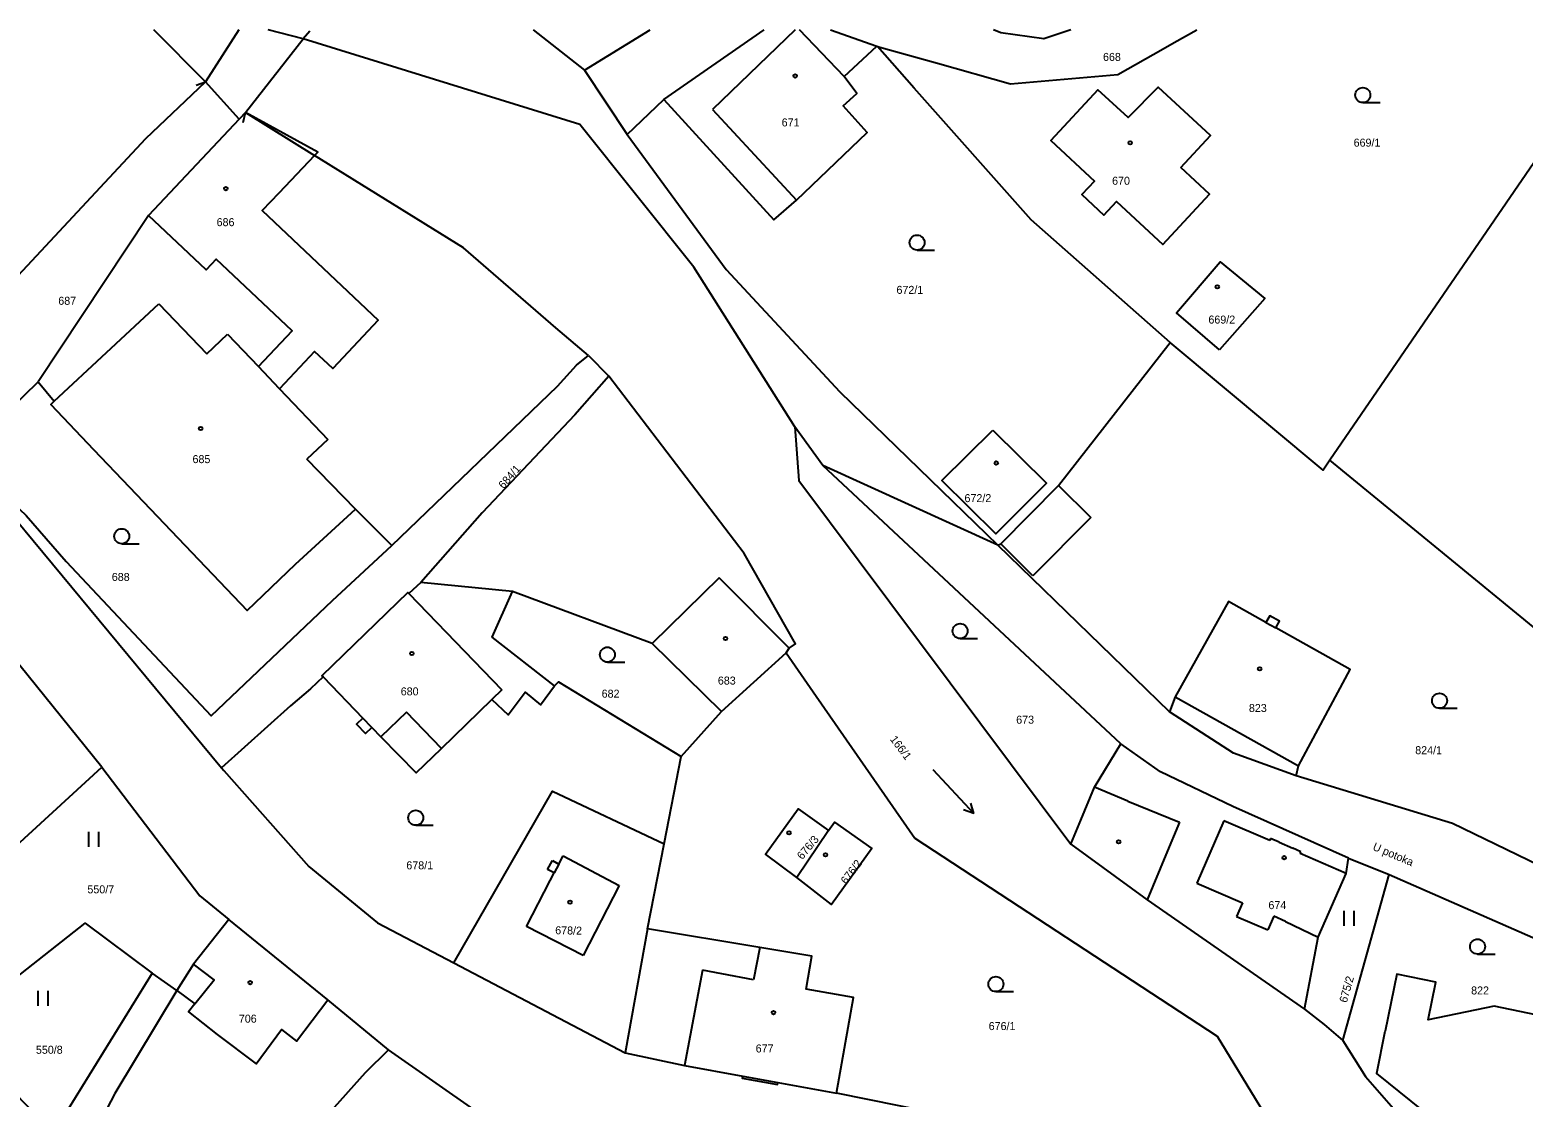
# Model space of a CAD drawing. Extents: x -719706 to -718922, y -950351 to -949651.
# Drawn here: x -719337.3 to -719188, y -949757.7 to -949651 of the extents above; entities that cross this region are included whole.
import ezdxf

# ---------------------------------------------------------------- set-up
doc = ezdxf.new("R2010")
doc.units = 0
doc.layers.add('Doplňující texty', color=7, linetype='Continuous')

msp = doc.modelspace()

# ---------------------------------------------------------------- linework, layer by layer
at = {"layer": 'Doplňující texty'}
for p, q in [((-719319.76, -949656.24), (-719324.91, -949651.04)), ((-719316.41, -949651.04), (-719319.76, -949656.24)), ((-719309.32, -949651.18), (-719309.98, -949651.93)), ((-719281.84, -949655.07), (-719275.29, -949651.04)), ((-719260.78, -949651.04), (-719269.05, -949659.01)), ((-719255.9, -949655.7), (-719260.35, -949651.04)), ((-719177.85, -949651.04), (-719207.33, -949694.07)), ((-719315.76, -949659.3), (-719309.98, -949651.93)), ((-719252.63, -949652.68), (-719252.56, -949652.7)), ((-719320.7, -949656.58), (-719319.76, -949656.24)), ((-719316.37, -949659.95), (-719319.76, -949656.24)), ((-719281.84, -949655.07), (-719277.6, -949661.51)), ((-719315.97, -949660.28), (-719315.76, -949659.3)), ((-719315.76, -949659.3), (-719308.84, -949663.6)), ((-719277.6, -949661.51), (-719273.91, -949658)), ((-719269.05, -949659.01), (-719260.66, -949668.05)), ((-719204.03, -949658.31), (-719202.28, -949658.31)), ((-719316.37, -949659.95), (-719325.45, -949669.59)), ((-719325.45, -949669.59), (-719336.48, -949686.23)), ((-719248.6, -949673.05), (-719246.85, -949673.05)), ((-719334.88, -949688.17), (-719324.42, -949678.41)), ((-719324.42, -949678.41), (-719319.62, -949683.42)), ((-719319.62, -949683.42), (-719317.54, -949681.45)), ((-719317.54, -949681.45), (-719314.45, -949684.7)), ((-719281.46, -949683.59), (-719279.41, -949685.67)), ((-719344.07, -949693.57), (-719336.48, -949686.23)), ((-719312.34, -949686.93), (-719307.53, -949691.99)), ((-719258.01, -949694.6), (-719260.83, -949690.71)), ((-719307.53, -949691.99), (-719309.62, -949693.96)), ((-719344.07, -949693.57), (-719318.16, -949724.8)), ((-719304.77, -949698.94), (-719309.62, -949693.96)), ((-719228.22, -949722.41), (-719258.01, -949694.6)), ((-719240.54, -949702.56), (-719258.01, -949694.6)), ((-719181.78, -949714.99), (-719207.33, -949694.07)), ((-719234.47, -949696.59), (-719231.24, -949699.79)), ((-719231.24, -949699.79), (-719237.01, -949705.61)), ((-719328.13, -949702.41), (-719326.38, -949702.41)), ((-719223.37, -949719.21), (-719240.54, -949702.56)), ((-719237.01, -949705.61), (-719240.24, -949702.41)), ((-719289.05, -949707.2), (-719298.21, -949706.3)), ((-719268.38, -949705.81), (-719275.1, -949712.37)), ((-719261.4, -949712.85), (-719268.38, -949705.81)), ((-719299.41, -949707.39), (-719290.11, -949717)), ((-719330.11, -949724.76), (-719341.41, -949710.76)), ((-719213.72, -949710.29), (-719212.74, -949710.83)), ((-719244.3, -949711.89), (-719242.55, -949711.89)), ((-719279.57, -949714.25), (-719277.82, -949714.25)), ((-719268.15, -949719.18), (-719261.7, -949713.32)), ((-719290.11, -949717), (-719291.12, -949717.98)), ((-719222.78, -949717.73), (-719210.47, -949724.62)), ((-719196.36, -949718.86), (-719194.61, -949718.86)), ((-719303.11, -949720.78), (-719304.02, -949719.84)), ((-719299.66, -949719.26), (-719302.21, -949721.72)), ((-719296.16, -949722.89), (-719299.66, -949719.26)), ((-719272.2, -949723.69), (-719268.15, -949719.18)), ((-719273.9, -949732.4), (-719272.2, -949723.69)), ((-719247.03, -949724.99), (-719242.94, -949729.38)), ((-719247.03, -949724.99), (-719242.94, -949729.38)), ((-719227.52, -949728.14), (-719230.86, -949726.76)), ((-719242.94, -949729.38), (-719243.97, -949729.01)), ((-719242.94, -949729.38), (-719243.97, -949729.01)), ((-719242.94, -949729.38), (-719243.24, -949728.33)), ((-719242.94, -949729.38), (-719243.24, -949728.33)), ((-719227.52, -949728.14), (-719222.35, -949730.25)), ((-719298.73, -949730.56), (-719296.98, -949730.56)), ((-719222.35, -949730.25), (-719223.74, -949733.52)), ((-719217.93, -949730.1), (-719220.62, -949736.34)), ((-719213.34, -949732.07), (-719217.93, -949730.1)), ((-719331.41, -949732.71), (-719331.41, -949731.21)), ((-719330.41, -949732.71), (-719330.41, -949731.21)), ((-719275.56, -949740.91), (-719273.9, -949732.4)), ((-719257.45, -949731.07), (-719260.64, -949735.78)), ((-719213.26, -949731.89), (-719213.34, -949732.07)), ((-719212.41, -949732.26), (-719213.26, -949731.89)), ((-719212.41, -949732.26), (-719211.03, -949732.85)), ((-719284.43, -949734.43), (-719284, -949733.6)), ((-719284, -949733.6), (-719278.38, -949736.58)), ((-719223.74, -949733.52), (-719225.6, -949738.01)), ((-719210.22, -949733.2), (-719211.03, -949732.85)), ((-719210.29, -949733.39), (-719210.22, -949733.2)), ((-719205.69, -949735.37), (-719210.29, -949733.39)), ((-719205.46, -949733.83), (-719201.4, -949735.49)), ((-719285.54, -949734.97), (-719285.07, -949734.09)), ((-719284.88, -949735.3), (-719285.54, -949734.97)), ((-719285.28, -949736.09), (-719284.88, -949735.3)), ((-719285.07, -949734.09), (-719284.43, -949734.43)), ((-719284.43, -949734.43), (-719284.88, -949735.3)), ((-719206.04, -949752.09), (-719201.4, -949735.49)), ((-719201.4, -949735.49), (-719174.77, -949747.18)), ((-719287.64, -949740.66), (-719285.28, -949736.09)), ((-719278.38, -949736.58), (-719279.58, -949738.92)), ((-719220.62, -949736.34), (-719216.06, -949738.3)), ((-719216.06, -949738.3), (-719216.65, -949739.66)), ((-719307.51, -949748.02), (-719317.42, -949739.96)), ((-719279.58, -949738.92), (-719281.99, -949743.57)), ((-719216.65, -949739.66), (-719213.52, -949741)), ((-719212.94, -949739.65), (-719213.52, -949741)), ((-719211.75, -949740.16), (-719212.94, -949739.65)), ((-719205.9, -949740.6), (-719205.9, -949739.1)), ((-719204.9, -949740.6), (-719204.9, -949739.1)), ((-719281.99, -949743.57), (-719287.64, -949740.66)), ((-719275.56, -949740.91), (-719277.79, -949753.32)), ((-719211.75, -949740.16), (-719208.51, -949741.75)), ((-719264.33, -949742.76), (-719264.96, -949746.02)), ((-719294.93, -949744.32), (-719277.79, -949753.32)), ((-719192.56, -949743.44), (-719190.81, -949743.44)), ((-719322.62, -949747.08), (-719325.08, -949745.33)), ((-719270.05, -949745.04), (-719271.87, -949754.57)), ((-719268.11, -949745.41), (-719270.05, -949745.04)), ((-719264.96, -949746.02), (-719268.11, -949745.41)), ((-719336.49, -949748.62), (-719336.49, -949747.12)), ((-719335.49, -949748.62), (-719335.49, -949747.12)), ((-719240.72, -949747.19), (-719238.97, -949747.19)), ((-719301.47, -949752.99), (-719307.51, -949748.02)), ((-719266.04, -949755.64), (-719262.53, -949756.28)), ((-719226.9, -949763.32), (-719256.67, -949757.35))]:
    msp.add_line(p, q, dxfattribs=at)
for points in [[(-719260.83, -949690.71), (-719270.93, -949674.77), (-719282.32, -949660.51), (-719309.98, -949651.93), (-719313.5, -949651.04)], [(-719286.98, -949651.04), (-719281.84, -949655.07)], [(-719273.91, -949658), (-719263.88, -949651.04)], [(-719257.25, -949651.04), (-719252.63, -949652.68)], [(-719252.56, -949652.7), (-719246.56, -949654.35), (-719239.27, -949656.43), (-719228.54, -949655.51), (-719223.98, -949652.93), (-719222.88, -949652.31), (-719220.63, -949651.04)], [(-719233.21, -949651.04), (-719235.91, -949651.93), (-719240.23, -949651.32), (-719240.97, -949651.04)], [(-719273.91, -949658), (-719262.93, -949670.03), (-719260.66, -949668.05), (-719253.59, -949661.28), (-719255.99, -949658.62), (-719254.63, -949657.4), (-719255.9, -949655.7), (-719252.63, -949652.68)], [(-719223.31, -949682.29), (-719237.18, -949670.04), (-719248.88, -949656.85), (-719252.56, -949652.7)], [(-719354.56, -949684.14), (-719348.21, -949683.77), (-719344.42, -949681.93), (-719325.72, -949661.88), (-719319.76, -949656.24)], [(-719222.24, -949664.78), (-719219.27, -949661.58), (-719224.5, -949656.78), (-719227.49, -949659.79), (-719230.52, -949657.03), (-719235.23, -949662.1), (-719230.85, -949666.15), (-719232.13, -949667.51), (-719229.93, -949669.57), (-719228.66, -949668.21), (-719224.03, -949672.5), (-719219.35, -949667.47), (-719222.24, -949664.78)], [(-719308.84, -949663.6), (-719308.52, -949663.27), (-719315.76, -949659.3), (-719316.37, -949659.95)], [(-719277.6, -949661.51), (-719267.68, -949674.99), (-719256.32, -949687.21), (-719240.54, -949702.56)], [(-719308.84, -949663.6), (-719312.41, -949667.36), (-719314.07, -949669.11), (-719302.48, -949680.05), (-719307.02, -949684.89), (-719308.85, -949683.2), (-719312.34, -949686.93), (-719314.45, -949684.7), (-719311.07, -949681.11), (-719318.67, -949673.95), (-719319.68, -949675.01), (-719325.45, -949669.59)], [(-719281.46, -949683.59), (-719284.73, -949680.84), (-719293.95, -949672.84), (-719308.84, -949663.6)], [(-719218.36, -949683.01), (-719222.65, -949679.33), (-719218.31, -949674.22), (-719213.82, -949677.89), (-719218.36, -949683.01)], [(-719240.54, -949702.56), (-719240.24, -949702.41), (-719234.47, -949696.59), (-719223.31, -949682.29)], [(-719207.33, -949694.07), (-719207.99, -949695.04), (-719223.31, -949682.29)], [(-719301.12, -949702.6), (-719284.56, -949686.67), (-719282.65, -949684.55), (-719281.46, -949683.59)], [(-719336.48, -949686.23), (-719334.88, -949688.17), (-719335.21, -949688.5), (-719330.95, -949692.98), (-719326.64, -949697.5), (-719315.59, -949709.07), (-719310.75, -949704.45), (-719304.77, -949698.94), (-719301.12, -949702.6)], [(-719279.41, -949685.67), (-719282.83, -949689.52), (-719292.08, -949699.32), (-719298.21, -949706.3)], [(-719261.7, -949713.32), (-719261.4, -949712.85), (-719260.75, -949712.42), (-719265.89, -949703.4), (-719279.41, -949685.67)], [(-719260.83, -949690.71), (-719260.41, -949696.09), (-719233.21, -949732.46)], [(-719241.03, -949691.04), (-719235.66, -949696.36), (-719240.71, -949701.43), (-719246.12, -949696.08), (-719241.03, -949691.04)], [(-719344.07, -949693.57), (-719337.7, -949699.6), (-719333.7, -949704.2), (-719319.2, -949719.6), (-719307.06, -949708.08), (-719301.12, -949702.6)], [(-719298.21, -949706.3), (-719299.41, -949707.39), (-719299.52, -949707.28), (-719308.11, -949715.6), (-719307.98, -949715.73)], [(-719284.84, -949716.62), (-719291.1, -949711.75), (-719289.05, -949707.2)], [(-719268.15, -949719.18), (-719275.1, -949712.37), (-719289.05, -949707.2)], [(-719210.69, -949725.61), (-719210.47, -949724.62), (-719205.31, -949714.98), (-719212.74, -949710.83), (-719212.37, -949710.16), (-719213.34, -949709.62), (-719213.72, -949710.29), (-719217.45, -949708.2), (-719222.78, -949717.73), (-719223.37, -949719.21)], [(-719261.7, -949713.32), (-719258.98, -949717.22), (-719258.68, -949717.65), (-719248.82, -949731.83), (-719218.61, -949751.63), (-719213.96, -949759.25), (-719217.32, -949765.25)], [(-719307.98, -949715.73), (-719309.25, -949716.91), (-719311.25, -949718.63), (-719318.16, -949724.8)], [(-719307.98, -949715.73), (-719304.02, -949719.84), (-719304.66, -949720.46), (-719303.76, -949721.39), (-719303.11, -949720.78), (-719302.21, -949721.72), (-719298.7, -949725.33), (-719296.16, -949722.89), (-719291.12, -949717.98), (-719289.5, -949719.5), (-719287.8, -949717.25), (-719286.25, -949718.5), (-719284.84, -949716.62)], [(-719284.84, -949716.62), (-719284.47, -949716.21), (-719272.2, -949723.69)], [(-719210.69, -949725.61), (-719216.96, -949723.35), (-719223.37, -949719.21)], [(-719233.21, -949732.46), (-719232.21, -949730.03), (-719230.86, -949726.76), (-719228.22, -949722.41)], [(-719205.46, -949733.83), (-719217.03, -949728.68), (-719224.25, -949725.2), (-719228.22, -949722.41)], [(-719351.71, -949744.34), (-719350.58, -949743.43), (-719340.35, -949734.1), (-719330.11, -949724.76)], [(-719330.11, -949724.76), (-719320.33, -949737.62), (-719317.42, -949739.96)], [(-719318.16, -949724.8), (-719317.92, -949725.08), (-719309.43, -949734.68), (-719302.55, -949740.32), (-719294.93, -949744.32)], [(-719184.25, -949735.62), (-719195.05, -949730.38), (-719210.69, -949725.61)], [(-719294.93, -949744.32), (-719285.05, -949727.16), (-719273.9, -949732.4)], [(-719260.64, -949735.78), (-719263.75, -949733.45), (-719260.48, -949728.91), (-719257.45, -949731.07)], [(-719257.45, -949731.07), (-719256.86, -949730.23), (-719253.11, -949732.88), (-719257.16, -949738.49), (-719260.64, -949735.78)], [(-719233.21, -949732.46), (-719225.6, -949738.01), (-719209.85, -949748.93)], [(-719209.85, -949748.93), (-719208.51, -949741.75), (-719205.69, -949735.37), (-719205.46, -949733.83)], [(-719317.42, -949739.96), (-719320.96, -949744.44), (-719322.62, -949747.08)], [(-719345.2, -949750.91), (-719331.79, -949740.33), (-719325.08, -949745.33)], [(-719256.67, -949757.35), (-719254.96, -949747.78), (-719259.7, -949746.94), (-719259.12, -949743.64), (-719264.33, -949742.76), (-719275.56, -949740.91)], [(-719320.81, -949748.4), (-719318.9, -949746.01), (-719320.96, -949744.44)], [(-719325.08, -949745.33), (-719333.47, -949758.94), (-719334.03, -949762.2), (-719345.2, -949750.91)], [(-719175.76, -949752.13), (-719179.99, -949750.91), (-719190.89, -949748.65), (-719197.5, -949750), (-719196.74, -949746.24), (-719200.64, -949745.44), (-719201.8, -949751.13), (-719201.82, -949751.19), (-719202.67, -949755.38), (-719193.56, -949762.7), (-719177.82, -949768.78)], [(-719322.62, -949747.08), (-719328.81, -949757.36), (-719331.3, -949762.1), (-719329.16, -949764.23), (-719319.85, -949773.28)], [(-719322.62, -949747.08), (-719320.81, -949748.4), (-719321.46, -949749.22), (-719318.6, -949751.47), (-719314.68, -949754.41), (-719312.14, -949750.99), (-719310.65, -949752.13), (-719307.51, -949748.02)], [(-719209.85, -949748.93), (-719207.91, -949750.46), (-719206.04, -949752.09)], [(-719301.47, -949752.99), (-719303.8, -949755.3), (-719319.85, -949773.28)], [(-719285.15, -949761.65), (-719289.5, -949760.2), (-719292.58, -949759.22), (-719301.47, -949752.99)], [(-719277.79, -949753.32), (-719271.87, -949754.57), (-719266.04, -949755.64), (-719266.08, -949755.84), (-719262.56, -949756.48), (-719262.53, -949756.28), (-719256.67, -949757.35)], [(-719206.04, -949752.09), (-719203.77, -949755.66), (-719191.88, -949769.27)]]:
    msp.add_lwpolyline(points, dxfattribs=at)
for centre, radius in [((-719260.79, -949655.64), 0.175), ((-719204.03, -949657.56), 0.75), ((-719227.3, -949662.33), 0.175), ((-719317.72, -949666.91), 0.175), ((-719248.6, -949672.3), 0.75), ((-719218.58, -949676.72), 0.175), ((-719320.23, -949690.89), 0.175), ((-719240.68, -949694.33), 0.175), ((-719328.13, -949701.66), 0.75), ((-719244.3, -949711.14), 0.75), ((-719279.57, -949713.5), 0.75), ((-719267.75, -949711.88), 0.175), ((-719299.12, -949713.38), 0.175), ((-719214.34, -949714.92), 0.175), ((-719196.36, -949718.11), 0.75), ((-719298.73, -949729.81), 0.75), ((-719261.4, -949731.31), 0.175), ((-719228.45, -949732.21), 0.175), ((-719257.76, -949733.51), 0.175), ((-719211.89, -949733.8), 0.175), ((-719283.3, -949738.24), 0.175), ((-719192.56, -949742.69), 0.75), ((-719240.72, -949746.44), 0.75), ((-719315.29, -949746.29), 0.175), ((-719262.96, -949749.29), 0.175)]:
    msp.add_circle(centre, radius, dxfattribs=at)

# ---------------------------------------------------------------- texts
for s, p in [('668', (-719230.01, -949654.14)), ('671', (-719262.14, -949660.69)), ('669/1', (-719204.95, -949662.71)), ('670', (-719229.1, -949666.52)), ('686', (-719318.64, -949670.66)), ('672/1', (-719250.66, -949677.43)), ('687', (-719334.47, -949678.52)), ('669/2', (-719219.47, -949680.4)), ('685', (-719321.05, -949694.35)), ('672/2', (-719243.86, -949698.25)), ('688', (-719329.12, -949706.13)), ('683', (-719268.52, -949716.49)), ('680', (-719300.23, -949717.57)), ('682', (-719280.14, -949717.8)), ('823', (-719215.42, -949719.23)), ('673', (-719238.69, -949720.4)), ('824/1', (-719198.79, -949723.45)), ('678/1', (-719299.67, -949734.96)), ('550/7', (-719331.56, -949737.36)), ('674', (-719213.47, -949738.94)), ('822', (-719193.2, -949747.47)), ('706', (-719316.42, -949750.29)), ('676/1', (-719241.44, -949751.03)), ('550/8', (-719336.71, -949753.4)), ('677', (-719264.74, -949753.27))]:
    msp.add_text(s, height=0.8, dxfattribs=at).set_placement(p)
for s, rotation, p in [('684/1', 49, (-719289.94, -949696.98)), ('166/1', 307, (-719251.35, -949721.97)), ('676/3', 50, (-719260.08, -949734.05)), ('U potoka', 337, (-719203.11, -949732.99)), ('676/2', 53, (-719255.67, -949736.52)), ('678/2', 359, (-719284.79, -949741.45)), ('675/2', 74, (-719205.64, -949748.35))]:
    msp.add_text(s, height=0.8, rotation=rotation, dxfattribs=at).set_placement(p)

doc.saveas('drawing.dxf')
